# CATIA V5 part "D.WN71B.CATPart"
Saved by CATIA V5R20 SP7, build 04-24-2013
Part number: D.WN71B
Material "Nessuno"
Bounding box of the stored display mesh (mm): x 0 to 150.807, y -135.185 to 0, z -91.151 to 75.737
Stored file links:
  C:\Users\designer2\Desktop\Ottobre 2022\25-10-2022\04\Yori Evo 48V\D.WN71B.CATPart
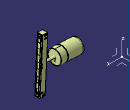
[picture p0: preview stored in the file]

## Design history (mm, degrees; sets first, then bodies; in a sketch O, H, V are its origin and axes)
AxisSystem1: origin (0, 0, 0), X (1, 0, 0), Y (0, 1, 0), Z (0, 0, 1)
Set1
  DatumSurface1
Body1 (main body), material "Nessuno"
